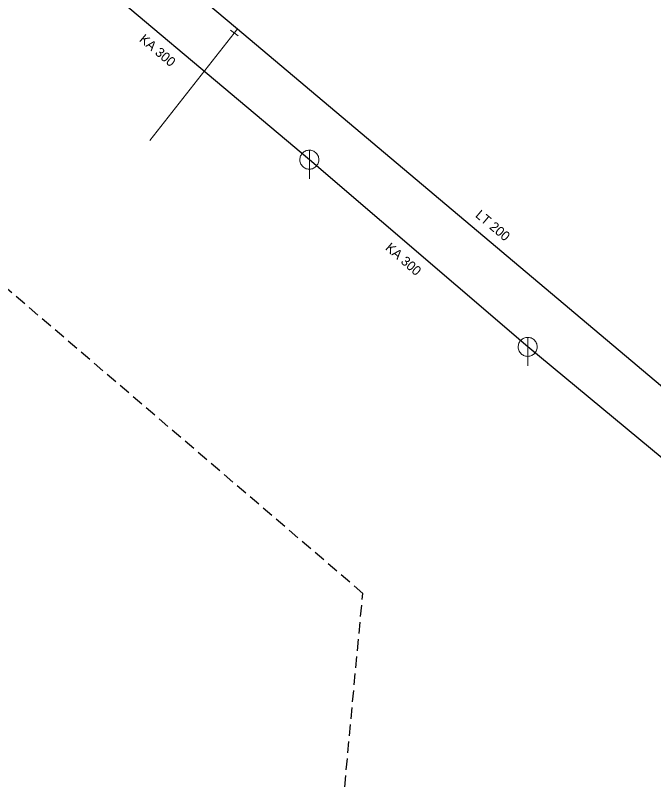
# Model space of a CAD drawing. Extents: x -790267 to -789874, y -989766 to -989454.
# Drawn here: x -790189.9 to -790122.7, y -989692.4 to -989612.1 of the extents above; entities that cross this region are included whole.
import ezdxf

# ---------------------------------------------------------------- set-up
doc = ezdxf.new("R2010")
doc.units = 0
doc.header["$LTSCALE"] = 0.4
doc.linetypes.add('MEDIUM_DASHED', pattern=[4.5, 3, -1.5])
doc.layers.add('1', color=7, linetype='Continuous')
for name, color, linetype, lineweight in [('13', 7, 'Continuous', 13), ('14', 7, 'Continuous', 13), ('17', 7, 'Continuous', 25), ('22', 7, 'Continuous', 13), ('34', 7, 'Continuous', 13), ('63', 7, 'MEDIUM_DASHED', 25)]:
    doc.layers.add(name, color=color, linetype=linetype, lineweight=lineweight)

msp = doc.modelspace()

# ---------------------------------------------------------------- linework, layer by layer
at = {"layer": '13'}
for p, q in [((-790166.475, -989613.482), (-790166.819, -989613.926)), ((-790166.819, -989613.926), (-790175.714, -989625.215))]:
    msp.add_line(p, q, dxfattribs=at)
at = {"layer": '14', "lineweight": 25}
msp.add_lwpolyline([(-790061.947, -989710.475), (-790095.515, -989680.27), (-790099.671, -989676.98), (-790135.954, -989646.924), (-790158.92, -989627.239), (-790187.694, -989603.019)], dxfattribs=at)
at = {"layer": '17'}
msp.add_lwpolyline([(-790176.006, -989605.454), (-790166.475, -989613.482), (-790103.748, -989666.305)], dxfattribs=at)
at = {"layer": '22'}
for p, q in [((-790158.92, -989629.239), (-790158.919, -989626.239)), ((-790135.954, -989648.924), (-790135.953, -989645.924))]:
    msp.add_line(p, q, dxfattribs=at)
for points in [[(-790157.92, -989627.239), (-790157.925, -989627.13), (-790157.943, -989627.022), (-790157.973, -989626.916), (-790158.013, -989626.815), (-790158.065, -989626.718), (-790158.127, -989626.628), (-790158.199, -989626.545), (-790158.279, -989626.471), (-790158.367, -989626.405), (-790158.461, -989626.35), (-790158.561, -989626.305), (-790158.666, -989626.272), (-790158.773, -989626.25), (-790158.882, -989626.24), (-790158.992, -989626.242), (-790159.1, -989626.256), (-790159.207, -989626.281), (-790159.31, -989626.318), (-790159.408, -989626.367), (-790159.5, -989626.425), (-790159.586, -989626.494), (-790159.663, -989626.571), (-790159.732, -989626.657), (-790159.791, -989626.749), (-790159.839, -989626.847), (-790159.876, -989626.95), (-790159.902, -989627.057), (-790159.916, -989627.165), (-790159.919, -989627.275), (-790159.909, -989627.384), (-790159.888, -989627.491), (-790159.854, -989627.595), (-790159.81, -989627.695), (-790159.755, -989627.79), (-790159.689, -989627.878), (-790159.615, -989627.958), (-790159.532, -989628.03), (-790159.442, -989628.092), (-790159.346, -989628.144), (-790159.244, -989628.185), (-790159.139, -989628.215), (-790159.031, -989628.233), (-790158.921, -989628.239), (-790158.812, -989628.233), (-790158.704, -989628.215), (-790158.599, -989628.186), (-790158.497, -989628.145), (-790158.4, -989628.093), (-790158.31, -989628.031), (-790158.227, -989627.96), (-790158.152, -989627.88), (-790158.087, -989627.792), (-790158.031, -989627.698), (-790157.987, -989627.598), (-790157.953, -989627.494), (-790157.931, -989627.386), (-790157.921, -989627.277)], [(-790134.954, -989646.924), (-790134.959, -989646.815), (-790134.977, -989646.707), (-790135.007, -989646.601), (-790135.047, -989646.5), (-790135.099, -989646.403), (-790135.161, -989646.313), (-790135.233, -989646.23), (-790135.313, -989646.156), (-790135.401, -989646.09), (-790135.495, -989646.035), (-790135.595, -989645.99), (-790135.7, -989645.957), (-790135.807, -989645.935), (-790135.916, -989645.925), (-790136.026, -989645.927), (-790136.134, -989645.941), (-790136.241, -989645.966), (-790136.344, -989646.003), (-790136.442, -989646.052), (-790136.534, -989646.11), (-790136.62, -989646.179), (-790136.697, -989646.256), (-790136.766, -989646.342), (-790136.825, -989646.434), (-790136.873, -989646.532), (-790136.91, -989646.635), (-790136.936, -989646.742), (-790136.95, -989646.85), (-790136.953, -989646.96), (-790136.943, -989647.069), (-790136.922, -989647.176), (-790136.888, -989647.28), (-790136.844, -989647.38), (-790136.789, -989647.475), (-790136.723, -989647.563), (-790136.649, -989647.643), (-790136.566, -989647.715), (-790136.476, -989647.777), (-790136.38, -989647.829), (-790136.278, -989647.87), (-790136.173, -989647.9), (-790136.065, -989647.918), (-790135.955, -989647.924), (-790135.846, -989647.918), (-790135.738, -989647.9), (-790135.633, -989647.871), (-790135.531, -989647.83), (-790135.434, -989647.778), (-790135.344, -989647.716), (-790135.261, -989647.645), (-790135.186, -989647.565), (-790135.121, -989647.477), (-790135.065, -989647.383), (-790135.021, -989647.283), (-790134.987, -989647.179), (-790134.965, -989647.071), (-790134.955, -989646.962)]]:
    msp.add_lwpolyline(points, close=True, dxfattribs=at)
at = {"layer": '34'}
msp.add_line((-790167.225, -989613.634), (-790166.413, -989614.218), dxfattribs=at)
at = {"layer": '63'}
msp.add_lwpolyline([(-790188.469, -989455.136), (-790139.344, -989496.446), (-790139.344, -989496.446), (-790029.929, -989518.217), (-790029.929, -989518.217), (-789963.498, -989555.061), (-789963.498, -989555.061), (-789946.75, -989559.527), (-789946.75, -989559.527), (-789908.79, -989634.89), (-789908.79, -989634.89), (-790051.142, -989765.519), (-790051.142, -989765.519), (-790157.208, -989714.719), (-790157.208, -989714.719), (-790153.3, -989672.851), (-790153.3, -989672.851), (-790266.065, -989576.274), (-790266.065, -989576.274), (-790235.362, -989502.586), (-790235.362, -989502.586), (-790189.028, -989455.694), (-790189.028, -989455.694)], close=True, dxfattribs=at)

# ---------------------------------------------------------------- texts
at = {"layer": '1'}
for s, rotation, p in [('KA 300', 320, (-790176.88, -989614.715)), ('LT 200', 320, (-790141.536, -989633.194)), ('KA 300', 319, (-790151.007, -989636.636))]:
    msp.add_text(s, height=1, rotation=rotation, dxfattribs=at).set_placement(p)

doc.saveas('drawing.dxf')
